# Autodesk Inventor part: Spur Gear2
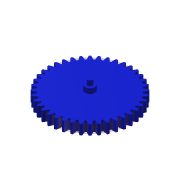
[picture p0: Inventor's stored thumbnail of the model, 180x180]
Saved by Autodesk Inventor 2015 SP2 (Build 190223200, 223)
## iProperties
Created: 2019-12
Part Number: Spur Gear2
Material: Steel
Document SubType Name: Modeling
Designer: Kuan_Lun Hsu
Categories: <?xml version="1.0" encoding="UTF-16"?> <MemberInstance><Categories><FamilyTemplate><FamilyTemplateParameter ValueType="xs:double" Id="1" ObjectReferenceKey="da
Density: 7.85 g/cm^3
Appearance: 藍色 - 牆面油漆 - 亮面
Mass: 396.011 g
Surface Area: 152.927 cm^2
Volume: 50.4473 cm^3
CustomPartVersion: 1
Author: Kuan_Lun Hsu
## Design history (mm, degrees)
sketch "Sketch1"
  geometry: C1 r 42 at (0, 0)
  constraints: 1 centre point
  dimensions: "d0" = 84 diameter of C1 (= da_da)
extrude "Extrusion1" new body sketch "Sketch1" distance "d1" = 10 (= da_b); taper "d2" = 0 deg
workplane "Work Plane2"
sketch "Sketch2"
  geometry: C1 r 42 at (0, 0) reference; C2 r 40 at (0, 0)
  constraints: 1 centre point, 1 coincident
  dimensions: "d3" = 80 diameter of C2 (= da_dw)
feature "節圓直徑" sketch "Sketch2" dims "d4" = 10, "d5" = 0
workplane "Work Plane8"
workplane "Work Plane9"
feature "正齒輪" dims "da_b" = 10, "da_d" = 80, "da_aw" = 60, "da_da" = 84, "da_df" = 75, "da_dw" = 80, angle "da_beta" = 0 deg, "da_lefttooth" = 0, "da_righttooth" = 0
sketch "草圖3"
  geometry: C1 r 5 at (0, 0); 1 further point
  constraints: 1 centre point, 1 coincident
  dimensions: "d49" = 10 diameter of C1
extrude "擠出2" join sketch "草圖3" distance "d50" = 5; taper "d51" = 0 deg
sketch "草圖4"
  geometry: C1 r 5 at (0, 0) reference; C2 r 2.5 at (0, 0); 1 further point
  constraints: 1 centre point, 1 coincident
  dimensions: "d52" = 5 diameter of C2
extrude "擠出3" join sketch "草圖4" distance "d53" = 5; taper "d54" = 0 deg
node "工作平面11"
sketch "草圖5"
  geometry: C1 r 5 at (0, 0) reference; C2 r 5 at (0, 0) reference; C3 r 40 at (0, 0); A1 r 22.322 centre (14.274, 35.943) between (-7.383, 41.346) and (-8.037, 36.629) reference; A2 r 37.5 centre (0, 0) between (-8.037, 36.629) and (-9.468, 36.285) reference; A3 r 22.322 centre (-29.037, 25.545) between (-9.468, 36.285) and (-12.192, 40.191) reference; A4 r 42 centre (0, 0) between (-12.192, 40.191) and (-13.76, 39.682) reference; A5 r 22.322 centre (8.476, 37.734) between (-13.76, 39.682) and (-13.668, 34.921) reference; A6 r 37.5 centre (0, 0) between (-13.668, 34.921) and (-15.028, 34.357) reference; A7 r 22.322 centre (-32.675, 20.688) between (-15.028, 34.357) and (-18.329, 37.789) reference; A8 r 42 centre (0, 0) between (-18.329, 37.789) and (-19.799, 37.041) reference; A9 r 22.322 centre (2.469, 38.595) between (-19.799, 37.041) and (-18.962, 32.353) reference; A10 r 37.5 centre (0, 0) between (-18.962, 32.353) and (-20.218, 31.583) reference; A11 r 22.322 centre (-35.509, 15.322) between (-20.218, 31.583) and (-24.015, 34.457) reference; A12 r 42 centre (0, 0) between (-24.015, 34.457) and (-25.349, 33.487) reference; A13 r 22.322 centre (-3.599, 38.506) between (-25.349, 33.487) and (-23.79, 28.988) reference; A14 r 37.5 centre (0, 0) between (-23.79, 28.988) and (-24.909, 28.032) reference; A15 r 22.322 centre (-37.469, 9.579) between (-24.909, 28.032) and (-29.11, 30.276) reference; A16 r 42 centre (0, 0) between (-29.11, 30.276) and (-30.276, 29.11) reference; A17 r 22.322 centre (-9.579, 37.469) between (-30.276, 29.11) and (-28.032, 24.909) reference; A18 r 37.5 centre (0, 0) between (-28.032, 24.909) and (-28.988, 23.79) reference; A19 r 22.322 centre (-38.506, 3.599) between (-28.988, 23.79) and (-33.487, 25.349) reference; A20 r 42 centre (0, 0) between (-33.487, 25.349) and (-34.457, 24.015) reference; A21 r 22.322 centre (-15.322, 35.509) between (-34.457, 24.015) and (-31.583, 20.218) reference; A22 r 37.5 centre (0, 0) between (-31.583, 20.218) and (-32.353, 18.962) reference; A23 r 22.322 centre (-38.595, -2.469) between (-32.353, 18.962) and (-37.041, 19.799) reference; A24 r 42 centre (0, 0) between (-37.041, 19.799) and (-37.789, 18.329) reference; A25 r 22.322 centre (-20.688, 32.675) between (-37.789, 18.329) and (-34.357, 15.028) reference; A26 r 37.5 centre (0, 0) between (-34.357, 15.028) and (-34.921, 13.668) reference; A27 r 22.322 centre (-37.734, -8.476) between (-34.921, 13.668) and (-39.682, 13.76) reference; A28 r 42 centre (0, 0) between (-39.682, 13.76) and (-40.191, 12.192) reference; A29 r 22.322 centre (-25.545, 29.037) between (-40.191, 12.192) and (-36.285, 9.468) reference; A30 r 37.5 centre (0, 0) between (-36.285, 9.468) and (-36.629, 8.037) reference; A31 r 22.322 centre (-35.943, -14.274) between (-36.629, 8.037) and (-41.346, 7.383) reference; A32 r 42 centre (0, 0) between (-41.346, 7.383) and (-41.604, 5.755) reference; A33 r 22.322 centre (-29.773, 24.683) between (-41.604, 5.755) and (-37.319, 3.676) reference; A34 r 37.5 centre (0, 0) between (-37.319, 3.676) and (-37.435, 2.208) reference; A35 r 22.322 centre (-33.268, -19.722) between (-37.435, 2.208) and (-41.992, 0.825) reference; A36 r 42 centre (0, 0) between (-41.992, 0.825) and (-41.992, -0.825) reference; A37 r 22.322 centre (-33.268, 19.722) between (-41.992, -0.825) and (-37.435, -2.208) reference; A38 r 37.5 centre (0, 0) between (-37.435, -2.208) and (-37.319, -3.676) reference; A39 r 22.322 centre (-29.773, -24.683) between (-37.319, -3.676) and (-41.604, -5.755) reference; A40 r 42 centre (0, 0) between (-41.604, -5.755) and (-41.346, -7.383) reference; A41 r 22.322 centre (-35.943, 14.274) between (-41.346, -7.383) and (-36.629, -8.037) reference; A42 r 37.5 centre (0, 0) between (-36.629, -8.037) and (-36.285, -9.468) reference; A43 r 22.322 centre (-25.545, -29.037) between (-36.285, -9.468) and (-40.191, -12.192) reference; A44 r 42 centre (0, 0) between (-40.191, -12.192) and (-39.682, -13.76) reference; A45 r 22.322 centre (-37.734, 8.476) between (-39.682, -13.76) and (-34.921, -13.668) reference; A46 r 37.5 centre (0, 0) between (-34.921, -13.668) and (-34.357, -15.028) reference; A47 r 22.322 centre (-20.688, -32.675) between (-34.357, -15.028) and (-37.789, -18.329) reference; A48 r 42 centre (0, 0) between (-37.789, -18.329) and (-37.041, -19.799) reference; A49 r 22.322 centre (-38.595, 2.469) between (-37.041, -19.799) and (-32.353, -18.962) reference; A50 r 37.5 centre (0, 0) between (-32.353, -18.962) and (-31.583, -20.218) reference; A51 r 22.322 centre (-15.322, -35.509) between (-31.583, -20.218) and (-34.457, -24.015) reference; A52 r 42 centre (0, 0) between (-34.457, -24.015) and (-33.487, -25.349) reference; A53 r 22.322 centre (-38.506, -3.599) between (-33.487, -25.349) and (-28.988, -23.79) reference; A54 r 37.5 centre (0, 0) between (-28.988, -23.79) and (-28.032, -24.909) reference; A55 r 22.322 centre (-9.579, -37.469) between (-28.032, -24.909) and (-30.276, -29.11) reference; A56 r 42 centre (0, 0) between (-30.276, -29.11) and (-29.11, -30.276) reference; A57 r 22.322 centre (-37.469, -9.579) between (-29.11, -30.276) and (-24.909, -28.032) reference; A58 r 37.5 centre (0, 0) between (-24.909, -28.032) and (-23.79, -28.988) reference; A59 r 22.322 centre (-3.599, -38.506) between (-23.79, -28.988) and (-25.349, -33.487) reference; A60 r 42 centre (0, 0) between (-25.349, -33.487) and (-24.015, -34.457) reference; A61 r 22.322 centre (-35.509, -15.322) between (-24.015, -34.457) and (-20.218, -31.583) reference; A62 r 37.5 centre (0, 0) between (-20.218, -31.583) and (-18.962, -32.353) reference; A63 r 22.322 centre (2.469, -38.595) between (-18.962, -32.353) and (-19.799, -37.041) reference; A64 r 42 centre (0, 0) between (-19.799, -37.041) and (-18.329, -37.789) reference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; 1 further point
  constraints: 1 centre point, 1 coincident
  dimensions: "d55" = 80 diameter of C3
feature "擠出表面2" sketch "草圖5" dims "d56" = 10, "d57" = 0
body "Solid1"
body "Srf1"
node "投影迴路1"
node "投影迴路2"
node "曲面2"
other parameters: "d17" = 0, "d34" = 4.5 deg (computed from da_z), "d39" = 0, "d41" = 0, "d47" = 0, "d48" = 0
